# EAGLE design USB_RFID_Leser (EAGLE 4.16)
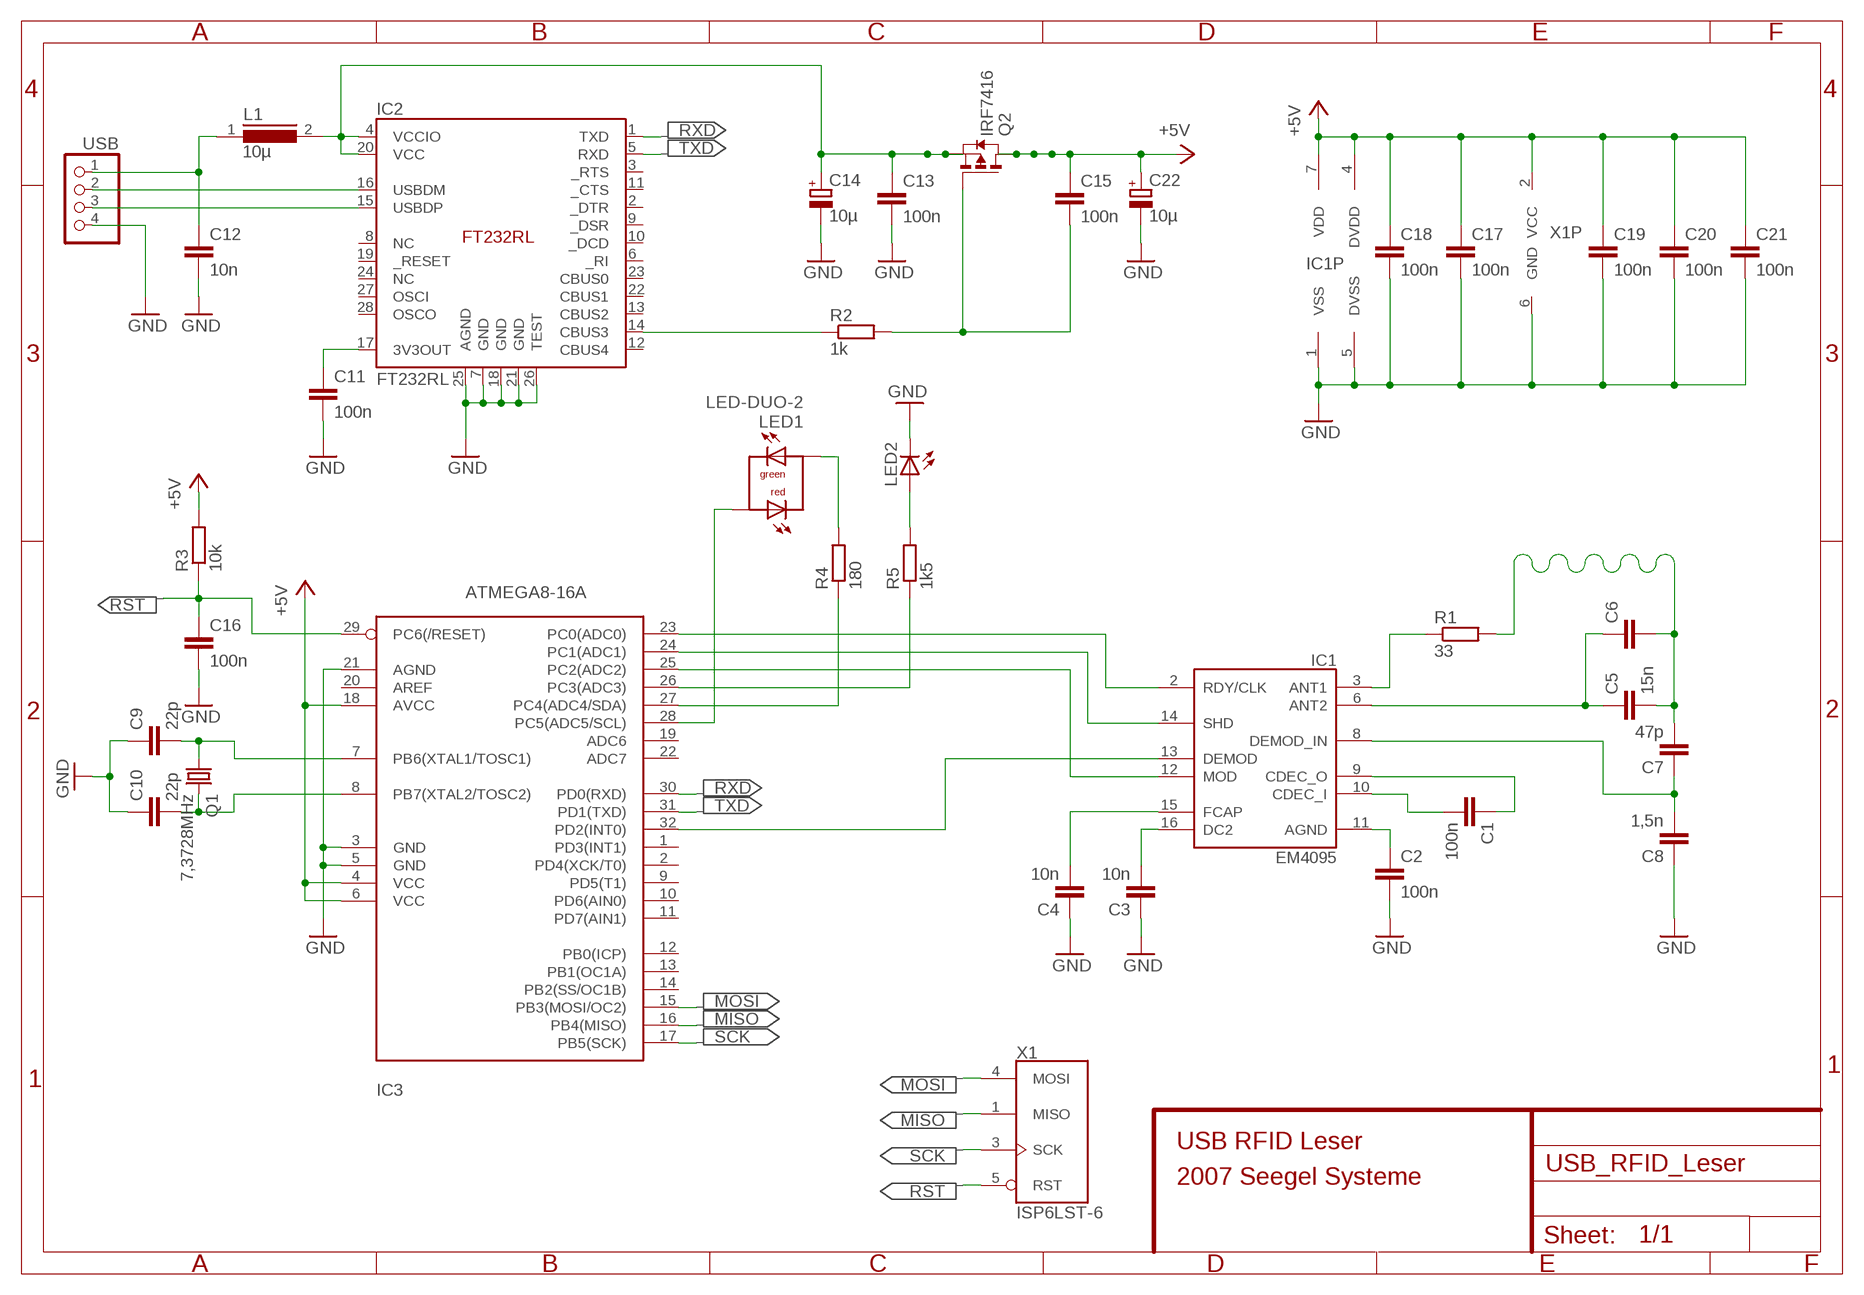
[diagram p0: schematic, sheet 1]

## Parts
C1  100n  C-EUC1206  [C1206]
C2  100n  C-EUC1206  [C1206]
C3  10n  C-EUC1206  [C1206]
C4  10n  C-EUC1206  [C1206]
C5  15n  C-EUC1206  [C1206]
C6  C-EUC1206  [C1206]
C7  47p  C-EUC1206  [C1206]
C8  1,5n  C-EUC1206  [C1206]
C9  22p  C-EUC1206  [C1206]
C10  22p  C-EUC1206  [C1206]
C11  100n  C-EUC1206  [C1206]
C12  10n  C-EUC1206  [C1206]
C13  100n  C-EUC1206  [C1206]
C14  10µ  CPOL-EU153CLV-0405  [153CLV-0405]
C15  100n  C-EUC1206  [C1206]
C16  100n  C-EUC1206  [C1206]
C17  100n  C-EUC1206  [C1206]
C18  100n  C-EUC1206  [C1206]
C19  100n  C-EUC1206  [C1206]
C20  100n  C-EUC1206  [C1206]
C21  100n  C-EUC1206  [C1206]
C22  10µ  CPOL-EU153CLV-0405  [153CLV-0405]
IC1  EM4095  [SO16]
IC2  FT232RL  [SSOP-28]
IC3  ATMEGA8-16A  [TQFP32-08]
L1  10µ  LQH3C  [LQH3C]
LED1  LED-DUO-2  [LED3MM]
LED2  LED3MM  [LED3MM]
Q1  7,3728MHz  CRYTALHC49S  [HC49/S]
Q2  IRF7416  PMOSSO8  [SO8]
R1  33  R-EU_R1206  [R1206]
R2  1k  R-EU_R1206  [R1206]
R3  10k  R-EU_R1206  [R1206]
R4  180  R-EU_R1206  [R1206]
R5  1k5  R-EU_R1206  [R1206]
USB  PINHD-1X4  [1X04]
X1  ISP6LST-6  [MA03-2]

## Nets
+5V: C15.1 C17.1 C18.1 C19.1 C20.1 C21.1 C22.+ IC1.4(DVDD) IC1.7(VDD) IC3.4(VCC) IC3.6(VCC) IC3.18(AVCC) Q2.5(D) Q2.6(D1) Q2.7(D2) Q2.8(D3) R3.2 X1.2(VCC)
GND: C2.2 C3.1 C4.1 C8.1 C9.1 C10.1 C11.2 C12.2 C13.2 C14.- C16.2 C17.2 C18.2 C19.2 C20.2 C21.2 C22.- IC1.1(VSS) IC1.5(DVSS) IC2.7(GND) IC2.18(GND) IC2.21(GND) IC2.25(AGND) IC2.26(TEST) IC3.3(GND) IC3.5(GND) IC3.21(AGND) LED2.K(C) USB.4 X1.6(GND)
MISO: IC3.16(PB4(MISO)) X1.1(MISO)
MOSI: IC3.15(PB3(MOSI/OC2)) X1.4(MOSI)
N$1: IC2.15(USBDP) USB.3
N$2: IC2.16(USBDM) USB.2
N$3: C1.2 IC1.10(CDEC_I)
N$4: C1.1 IC1.9(CDEC_O)
N$5: C2.1 IC1.11(AGND)
N$6: C3.2 IC1.16(DC2)
N$7: C4.2 IC1.15(FCAP)
N$8: IC1.3(ANT1) R1.1
N$9: IC1.2(RDY/CLK) IC3.23(PC0(ADC0))
N$10: C5.1 C6.1 IC1.6(ANT2)
N$11: C7.1 C8.2 IC1.8(DEMOD_IN)
N$12: C9.2 IC3.7(PB6(XTAL1/TOSC1)) Q1.1
N$13: C10.2 IC3.8(PB7(XTAL2/TOSC2)) Q1.2
N$14: IC1.13(DEMOD) IC3.32(PD2(INT0))
N$15: C11.1 IC2.17(3V3OUT)
N$16: C5.2 C6.2 C7.2 R1.2
N$17: C12.1 L1.1 USB.1
N$18: C13.1 C14.+ IC2.4(VCCIO) IC2.20(VCC) L1.2 Q2.1(S) Q2.2(S1) Q2.3(S2)
N$19: IC1.14(SHD) IC3.24(PC1(ADC1))
N$20: IC1.12(MOD) IC3.25(PC2(ADC2))
N$21: IC2.14(CBUS3) R2.1
N$22: C15.2 Q2.4(G) R2.2
N$23: IC3.26(PC3(ADC3)) R5.1
N$24: IC3.27(PC4(ADC4/SDA)) R4.1
N$25: LED1.K R4.2
N$26: IC3.28(PC5(ADC5/SCL)) LED1.A
N$27: LED2.A R5.2
RST: C16.1 IC3.29(PC6(/RESET)) R3.1 X1.5(RST)
RXD: IC2.1(TXD) IC3.30(PD0(RXD))
SCK: IC3.17(PB5(SCK)) X1.3(SCK)
TXD: IC2.5(RXD) IC3.31(PD1(TXD))
Unconnected: IC2.2(_DTR) IC2.3(_RTS) IC2.6(_RI) IC2.8(NC) IC2.9(_DSR) IC2.10(_DCD) IC2.11(_CTS) IC2.12(CBUS4) IC2.13(CBUS2) IC2.19(_RESET) IC2.22(CBUS1) IC2.23(CBUS0) IC2.24(NC) IC2.27(OSCI) IC2.28(OSCO) IC3.1(PD3(INT1)) IC3.2(PD4(XCK/T0)) IC3.9(PD5(T1)) IC3.10(PD6(AIN0)) IC3.11(PD7(AIN1)) IC3.12(PB0(ICP)) IC3.13(PB1(OC1A)) IC3.14(PB2(SS/OC1B)) IC3.19(ADC6) IC3.20(AREF) IC3.22(ADC7)

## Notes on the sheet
- USB RFID Leser
- 2007 Seegel Systeme

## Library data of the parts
C1-C13 C15-C21 = rcl:C-EU: CAPACITOR, European symbol
C14 C22 = rcl:CPOL-EU: POLARIZED CAPACITOR, European symbol
IC1 = emtec:EM4095: Read/Write analog front end for 125kHz RFID Basestation EM Microelectronic, http://www.emmicroelectronic.com
IC2 = ftdi4:FT232RL
IC3 = avr:ATMEGA8: MICROCONTROLLER 8 Kbytes FLASH 1 kbytes SRAM 512 bytes EEPROM USART 6-channel 10 bit ADC 2-channel 8 bit ADC
L1 = inductor-murata:LQH3C
LED1 = led:LED-DUO-2
LED2 = led:LED: LED
Q1 = crystal:CRYTAL: CRYSTAL
Q2 = zetex:PMOSSO8
R1-R5 = rcl:R-EU_: RESISTOR, European symbol
USB = pinhead:PINHD-1X4: PIN HEADER
X1 = avr:ISP6

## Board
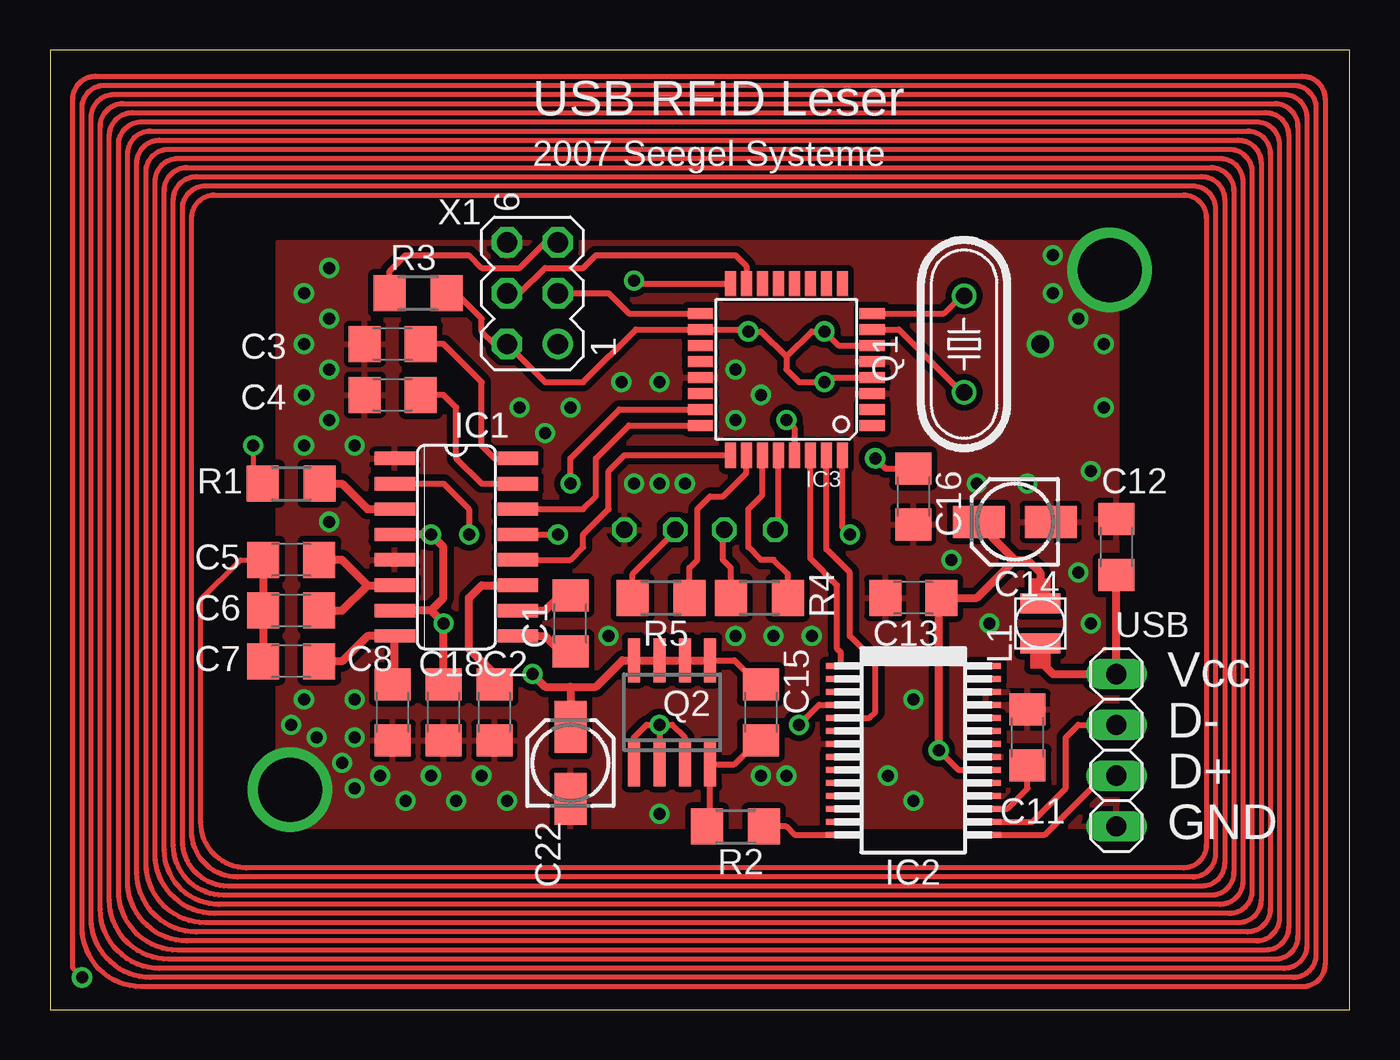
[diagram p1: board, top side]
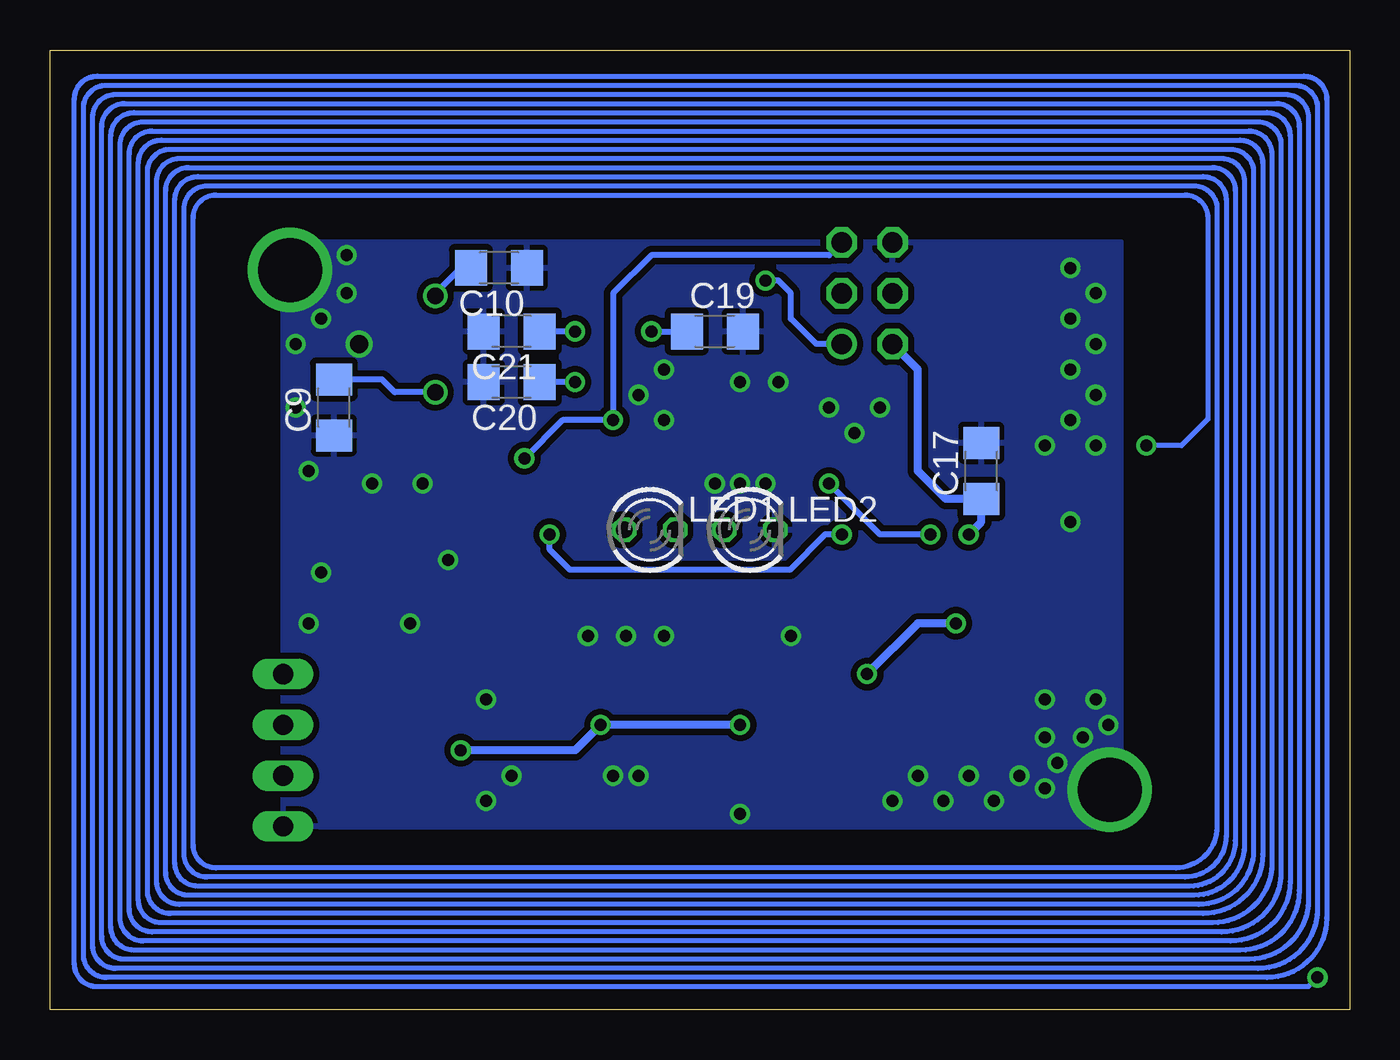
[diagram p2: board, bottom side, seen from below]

Size 65 x 48 mm. Coordinates in mm from the lower left corner, seen from the top.
Outline: 0,0 65,0 65,48 0,48 0,0
Copper layers (1*16): Top 0.035mm / dielectric 1.5mm / Bottom 0.035mm
Design rules "pcb-pool": minimum track width 6mil, minimum drill 12mil, track to track 6mil, track to pad 6mil, pad to pad 6mil, via to via 6mil, smd to smd 8mil, copper to edge 40mil, drill to drill 20mil, minimum pad ring 8mil, minimum via ring 8mil, stop-mask expansion 6mil, vias tented up to drill 0mil, thermal gap 10mil

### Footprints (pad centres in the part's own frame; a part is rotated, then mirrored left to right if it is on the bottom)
C1206 = smd 1.6 x 1.8: 1 -1.4,0; 2 1.4,0
153CLV-0405 = smd 2.6 x 1.6: + 1.8,0; - -1.8,0
SO16 = smd 0.66 x 2.032: 1 -4.445,-3.073; 2 -3.175,-3.073; 3 -1.905,-3.073; 4 -0.635,-3.073; 5 0.635,-3.073; 6 1.905,-3.073; 7 3.175,-3.073; 8 4.445,-3.073; 9 4.445,3.073; 10 3.175,3.073; 11 1.905,3.073; 12 0.635,3.073; 13 -0.635,3.073; 14 -1.905,3.073; 15 -3.175,3.073; 16 -4.445,3.073
SSOP-28 = smd 0.3 x 1.5: 1 -4.225,-3.625; 2 -3.575,-3.625; 3 -2.925,-3.625; 4 -2.275,-3.625; 5 -1.625,-3.625; 6 -0.975,-3.625; 7 -0.325,-3.625; 8 0.325,-3.625; 9 0.975,-3.625; 10 1.625,-3.625; 11 2.275,-3.625; 12 2.925,-3.625; 13 3.575,-3.625; 14 4.225,-3.625; 15 4.225,3.625; 16 3.575,3.625; 17 2.925,3.625; 18 2.275,3.625; 19 1.625,3.625; 20 0.975,3.625; 21 0.325,3.625; 22 -0.325,3.625; 23 -0.975,3.625; 24 -1.625,3.625; 25 -2.275,3.625; 26 -2.925,3.625; 27 -3.575,3.625; 28 -4.225,3.625
TQFP32-08 = smd 1.27 x 0.559: 1 -4.293,2.8; 2 -4.293,2; 3 -4.293,1.2; 4 -4.293,0.4; 5 -4.293,-0.4; 6 -4.293,-1.2; 7 -4.293,-2; 8 -4.293,-2.8; 17 4.293,-2.8; 18 4.293,-2; 19 4.293,-1.2; 20 4.293,-0.4; 21 4.293,0.4; 22 4.293,1.2; 23 4.293,2; 24 4.293,2.8 | smd 0.559 x 1.27: 9 -2.8,-4.293; 10 -2,-4.293; 11 -1.2,-4.293; 12 -0.4,-4.293; 13 0.4,-4.293; 14 1.2,-4.293; 15 2,-4.293; 16 2.8,-4.293; 25 2.8,4.293; 26 2,4.293; 27 1.2,4.293; 28 0.4,4.293; 29 -0.4,4.293; 30 -1.2,4.293; 31 -2,4.293; 32 -2.8,4.293
LQH3C = smd 1 x 2: 1 -1,0; 2 1,0
LED3MM = drill 0.813 octagon: A -1.27,0; K 1.27,0
HC49/S = drill 0.813 round: 1 -2.413,0; 2 2.413,0
SO8 = smd 0.6 x 2.2: 1 -1.905,-2.6; 2 -0.635,-2.6; 3 0.635,-2.6; 4 1.905,-2.6; 5 1.905,2.6; 6 0.635,2.6; 7 -0.635,2.6; 8 -1.905,2.6
R1206 = smd 1.6 x 1.803: 1 -1.422,0; 2 1.422,0
1X04 = drill 1.016 long: 1 -3.81,0; 2 -1.27,0; 3 1.27,0; 4 3.81,0
MA03-2 = drill 1.016 round: 1 -2.54,-1.27 | drill 1.016 octagon: 2 -2.54,1.27; 3 0,-1.27; 4 0,1.27; 5 2.54,-1.27; 6 2.54,1.27

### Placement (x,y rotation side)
C1  26.04,19.32 90 top
C2  22.23,14.88 270 top
C3  17.14,33.29 0 top
C4  17.14,30.75 0 top
C5  12.06,22.5 180 top
C6  12.06,19.95 180 top
C7  12.06,17.41 180 top
C8  17.14,14.88 90 top
C9  50.8,30.11 90 bottom
C10  42.55,37.1 180 bottom
C11  48.9,13.61 90 top
C12  53.34,23.13 90 top
C13  43.18,20.59 180 top
C14  48.26,24.4 180 top
C15  35.56,14.88 270 top
C16  43.18,25.67 270 top
C17  18.41,26.94 90 bottom
C18  19.68,14.88 270 top
C19  31.75,33.92 0 bottom
C20  41.91,31.38 180 bottom
C21  41.91,33.92 180 bottom
C22  26.04,12.34 90 top
IC1  20.32,23.13 270 top
IC2  43.18,12.97 270 top
IC3  36.83,32.02 180 top
L1  49.53,19.32 90 top
LED1  35,24 0 bottom
LED2  30,24 0 bottom
Q1  45.72,33.29 90 top
Q2  31.11,14.88 0 top
R1  12.06,26.3 180 top
R2  34.29,9.16 180 top
R3  18.41,35.83 0 top
R4  35.48,20.59 180 top
R5  30.56,20.59 180 top
USB  53.34,12.97 270 top
X1  24.13,35.83 90 top

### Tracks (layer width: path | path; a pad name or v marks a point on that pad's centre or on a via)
+5V  (via drill 0.6)
  Top 0.305: IC3.6 39.44,33.22 v38.73,33.92 38.1,33.92 36.83,32.66 | IC3.4 38.97,31.62 v38.73,31.38 37.47,31.38 36.83,32.02 36.83,32.66 | C15.1 35.56,16.14 34.23,17.48 Q2.5 | Q2.6 31.75,17.41 31.81,17.48 | Q2.7 30.48,17.41 30.54,17.48 | Q2.8 29.21,17.41 29.27,17.48 | 36.83,32.66 35.56,33.92 v34.92,33.92 34.83,34.02 IC3.18 29.3,34.02 26.67,31.38 24.77,31.38 X1.2 22.23,33.29 21.59,33.92 21.59,34.56 20.32,35.83 R3.2
  Top 0.406: 19.05,19.95 v19.68,19.32 C18.1 19.05,16.14 | 19.05,19.95 IC1.7 | 19.05,19.95 19.68,20.59 19.68,23.13 v19.05,23.77 IC1.4 17.14,23.77 | 31.81,17.48 Q2.5 | 30.54,17.48 Q2.6 | 29.27,17.48 Q2.7 | Q2.8 28.64,17.48 27.3,16.14 26.04,16.14 | 26.04,16.14 24.77,16.14 v24.13,16.78 | 26.04,16.14 C22.+
  Bottom 0.305: v34.92,33.92 C19.1 | v38.73,33.92 C21.1 | v38.73,31.38 C20.1
  Bottom 0.406: v19.05,23.77 18.41,24.4 C17.1 20.19,25.54 21.59,26.94 21.59,32.02 X1.2 | v24.13,16.78 21.59,19.32 v19.68,19.32
GND  (via drill 0.6, 0.9, 3.2)
  other vias: 12,11 34.29,32.02 35.56,30.75 34.29,29.48 23.5,30.11 26.04,30.11 28.57,31.38 30.48,31.38 12.7,33.29 13.97,32.02 12.7,30.75 13.97,29.48 12.7,28.21 15.24,28.21 15.24,11.06 17.78,10.43 19.05,11.7 20.32,10.43 21.59,11.7 22.86,10.43 35.56,11.7 36.83,11.7 43.18,15.51 43.18,10.43 52.07,26.94 49.53,33.29 46.99,19.32 52.07,19.32 51.44,21.86 13.97,24.4 16.51,11.7 15.24,13.61 15.24,15.51 13.34,13.61 12.7,15.51 14.61,12.34 12.06,14.24 38.1,18.68 36.2,18.68 34.29,18.68 27.94,18.68 31.75,26.3 29.21,26.3 30.48,26.3 24.77,28.84 12.7,35.83 13.97,37.1 13.97,34.56 30.48,9.79 41.91,11.7 45.09,22.5 46.35,26.3 48.9,26.3 52.7,33.29 52.7,30.11 53,37 50.16,37.73 50.16,35.83 51.44,34.56
  pour Bottom (isolate 0.305): 11.43,38.37 53.34,38.37 53.34,9.16 11.43,9.16
  pour Top (isolate 0.305): 11.43,38.37 53.34,38.37 53.34,9.16 11.43,9.16
MISO  (via drill 0.6)
  Top 0.305: IC3.16 29.36,36.31 v29.21,36.47
  Bottom 0.305: X1.1 26.67,33.29 27.94,34.56 27.94,35.83 28.57,36.47 v29.21,36.47
MOSI
  Top 0.305: X1.4 23.5,35.83 24.77,37.1 26.67,37.1 27.3,37.73 34.29,37.73 34.83,37.2 IC3.15
N$1
  Top 0.305: IC2.15 49.75,8.74 52.7,11.7 USB.3
N$2
  Top 0.305: IC2.16 49.13,9.39 50.8,11.06 50.8,13.61 51.44,14.24 USB.2
N$3
  Top 0.406: IC1.10 24.77,19.95 25.4,20.59 26.04,20.59 C1.2
N$4
  Top 0.406: IC1.9 24.77,18.68 25.4,18.05 26.04,18.05 C1.1
N$5
  Top 0.406: IC1.11 21.59,21.23 20.95,20.59 20.95,18.05 22.23,16.78 C2.1 21.59,16.14
N$6
  Top 0.305: IC1.16 22.23,27.57 21.59,28.21 21.59,31.38 19.68,33.29 C3.2
N$7
  Top 0.305: IC1.15 21.59,26.3 20.32,27.57 20.32,30.11 19.68,30.75 C4.2
N$8
  Top 0.406: IC1.3 15.88,25.04 14.61,26.3 R1.1 13.34,26.3
N$9  (via drill 0.6)
  Top 0.305: IC1.2 19.68,26.3 20.95,25.04 v20.95,23.77 | IC3.23 28.48,30.02 26.04,27.57 v26.04,26.3
  Bottom 0.305: v20.95,23.77 23.5,23.77 v26.04,26.3
N$10
  Top 0.406: 15.88,21.23 IC1.6 | 15.88,21.23 14.61,22.5 C5.1 13.34,21.86 | C6.1 14.61,19.95 15.88,21.23
N$11
  Top 0.305: C8.2 17.14,16.14 17.25,16.25
  Top 0.406: 13.34,16.78 C7.1 14.61,17.41 15.88,18.68 IC1.8 17.25,16.25
N$12
  Top 0.305: IC3.7 42.45,34.02 45.59,30.88 Q1.1
  Bottom 0.305: C9.2 48.39,31.52 47.75,30.88 Q1.1
N$13
  Top 0.305: Q1.2 45.72,35.83 44.71,34.82 IC3.8
  Bottom 0.305: Q1.2 45.72,35.83 44.45,37.1 C10.2
N$14  (via drill 0.6)
  Top 0.305: IC3.32 39.63,24.14 v40.01,23.77 | IC1.13 v25.4,23.77
  Bottom 0.305: v25.4,23.77 26.23,23.77 28,22 39,22 40.01,23 v40.01,23.77
N$15
  Top 0.305: IC2.17 47.88,10.04 48.9,11.06 C11.1 48.9,12.34
N$16  (via drill 0.6)
  Top 0.254: v1.6,1.6 1.14,2.06 1.14,45.55 arc-90 2.29,46.69 62.64,46.69 arc-90 63.78,45.55 63.78,2.29 arc-90 62.64,1.14 4.57,1.14 arc-90 1.6,4.12 1.6,45.09 arc-90 2.74,46.23 62.18,46.23 arc-90 63.32,45.09 63.32,2.74 arc-90 62.18,1.6 5.03,1.6 arc-90 2.06,4.57 2.06,44.63 arc-90 3.2,45.78 61.72,45.78 arc-90 62.87,44.63 62.87,3.2 arc-90 61.72,2.06 5.49,2.06 arc-90 2.52,5.03 2.52,44.18 arc-90 3.66,45.32 61.27,45.32 arc-90 62.41,44.18 62.41,3.66 arc-90 61.27,2.52 5.94,2.52 arc-90 2.97,5.49 2.97,43.72 arc-90 4.12,44.86 60.81,44.86 arc-90 61.95,43.72 61.95,4.12 arc-90 60.81,2.97 6.4,2.97 arc-90 3.43,5.94 3.43,43.26 arc-90 4.57,44.41 60.35,44.41 arc-90 61.49,43.26 61.49,4.57 arc-90 60.35,3.43 6.86,3.43 arc-90 3.89,6.4 3.89,42.81 arc-90 5.03,43.95 59.89,43.95 arc-90 61.04,42.81 61.04,5.03 arc-90 59.89,3.89 7.32,3.89 arc-90 4.34,6.86 4.34,42.35 arc-90 5.49,43.49 59.44,43.49 arc-90 60.58,42.35 60.58,5.49 arc-90 59.44,4.34 7.77,4.34 arc-90 4.8,7.31 4.8,41.89 arc-90 5.94,43.03 58.98,43.03 arc-90 60.12,41.89 60.12,5.94 arc-90 58.98,4.8 8.23,4.8 arc-90 5.26,7.77 5.26,41.43 arc-90 6.4,42.58 58.52,42.58 arc-90 59.66,41.43 59.66,6.4 arc-90 58.52,5.26 8.46,5.26 arc-90 5.71,8 5.71,40.98 arc-90 6.86,42.12 58.06,42.12 arc-90 59.21,40.98 59.21,6.86 arc-90 58.06,5.71 8.69,5.71 arc-90 6.17,8.23 6.17,40.52 arc-90 7.32,41.66 57.61,41.66 arc-90 58.75,40.52 58.75,7.31 arc-90 57.61,6.17 8.91,6.17 arc-90 6.63,8.46 6.63,40.06 arc-90 7.77,41.2 57.15,41.2 arc-90 58.29,40.06 58.29,7.77 arc-90 57.15,6.63 9.37,6.63 arc-90 7.09,8.91 7.09,39.6 arc-90 8.23,40.75 56.69,40.75 arc-90 57.84,39.6 57.84,8.23 arc-90 56.69,7.09 9.83,7.09 arc-90 7.54,9.37 7.54,20.51 9.53,22.5 C5.2
  Top 0.254: R1.2 10.16,26.79 v10.16,28.21
  Top 0.305: C5.2 10.79,21.86
  Top 0.406: C5.2 10.66,19.45 10.79,19.32 C6.2 10.66,16.91 10.79,16.78 C7.2
  Bottom 0.254: v1.6,1.6 2.06,1.14 62.64,1.14 arc90 63.78,2.29 63.78,45.55 arc90 62.64,46.69 2.29,46.69 arc90 1.14,45.55 1.14,4.57 arc90 4.12,1.6 62.18,1.6 arc90 63.32,2.74 63.32,45.09 arc90 62.18,46.23 2.74,46.23 arc90 1.6,45.09 1.6,5.03 arc90 4.57,2.06 61.72,2.06 arc90 62.87,3.2 62.87,44.63 arc90 61.72,45.78 3.2,45.78 arc90 2.06,44.63 2.06,5.49 arc90 5.03,2.52 61.27,2.52 arc90 62.41,3.66 62.41,44.18 arc90 61.27,45.32 3.66,45.32 arc90 2.52,44.18 2.52,5.94 arc90 5.49,2.97 60.81,2.97 arc90 61.95,4.12 61.95,43.72 arc90 60.81,44.86 4.12,44.86 arc90 2.97,43.72 2.97,6.4 arc90 5.94,3.43 60.35,3.43 arc90 61.49,4.57 61.49,43.26 arc90 60.35,44.41 4.57,44.41 arc90 3.43,43.26 3.43,6.86 arc90 6.4,3.89 59.89,3.89 arc90 61.04,5.03 61.04,42.81 arc90 59.89,43.95 5.03,43.95 arc90 3.89,42.81 3.89,7.31 arc90 6.86,4.34 59.44,4.34 arc90 60.58,5.49 60.58,42.35 arc90 59.44,43.49 5.49,43.49 arc90 4.34,42.35 4.34,7.77 arc90 7.32,4.8 58.98,4.8 arc90 60.12,5.94 60.12,41.89 arc90 58.98,43.03 5.94,43.03 arc90 4.8,41.89 4.8,8 arc90 7.54,5.26 58.52,5.26 arc90 59.66,6.4 59.66,41.43 arc90 58.52,42.58 6.4,42.58 arc90 5.26,41.43 5.26,8.23 arc90 7.77,5.71 58.06,5.71 arc90 59.21,6.86 59.21,40.98 arc90 58.06,42.12 6.86,42.12 arc90 5.71,40.98 5.71,8.46 arc90 8,6.17 57.61,6.17 arc90 58.75,7.31 58.75,40.52 arc90 57.61,41.66 7.32,41.66 arc90 6.17,40.52 6.17,8.69 arc90 8.23,6.63 57.15,6.63 arc90 58.29,7.77 58.29,40.06 arc90 57.15,41.2 7.77,41.2 arc90 6.63,40.06 6.63,9.14 arc90 8.69,7.09 56.69,7.09 arc90 57.84,8.23 57.84,39.6 arc90 56.69,40.75 8.23,40.75 arc90 7.09,39.6 7.09,29.53 8.41,28.21 v10.16,28.21
N$17
  Top 0.406: C12.1 USB.1 50.16,16.78 49.53,17.41 L1.1
N$18  (via drill 0.6)
  Top 0.305: IC2.20 45.42,11.99 v44.45,12.97 | 44.45,20.59 C13.1 | IC2.4 38.47,15.25 v37.47,14.24 | v30.48,14.24 Q2.2 | Q2.1 29.21,13.61 29.84,14.24 v30.48,14.24 | Q2.3 31.75,13.61 31.11,14.24 v30.48,14.24
  Top 0.406: L1.2 49.53,21.86 48.9,22.5 48.26,22.5 | C13.1 46.35,20.59 48.26,22.5 | v44.45,12.97 44.45,20.59 | C14.+ 46.35,24.4 48.26,22.5
  Bottom 0.406: v44.45,12.97 38.73,12.97 v37.47,14.24 v30.48,14.24
N$19
  Top 0.305: IC3.24 28.95,29.22 27.3,27.57 27.3,25.67 26.67,25.04 IC1.14
N$20
  Top 0.305: IC3.25 28.73,27.73 27.94,26.94 27.94,25.04 26.67,23.77 26.67,23.13 26.04,22.5 IC1.12
N$21
  Top 0.305: R2.1 36.83,9.16 37.24,8.74 IC2.14
N$22
  Top 0.305: R2.2 33.02,9.16 Q2.4 34.23,12.28 35.56,13.61 C15.2
N$23
  Top 0.305: R5.1 31.98,22.09 32.38,22.5 32.38,25.04 33.02,25.67 33.66,25.67 34.83,26.84 IC3.26
N$24
  Top 0.305: IC3.27 35.63,25.74 34.92,25.04 34.92,23.13 35.56,22.5 36.2,22.5 36.9,21.79 R4.1
N$25
  Top 0.305: R4.2 34.06,22.09 33.66,22.5 33.66,23.77 33.73,23.84 LED1.K
N$26
  Top 0.305: LED1.A 36.27,24.09 36.43,24.25 IC3.28
N$27
  Top 0.305: LED2.A 31.27,23.92 29.14,21.79 R5.2
RST  (via drill 0.6)
  Top 0.305: IC3.29 37.23,29.08 v36.83,29.48 | C16.1 41.78,27.07 v41.27,27.57 | X1.5 24.77,38.37 23.5,37.1 21.59,37.1 20.95,37.73 17.78,37.73 16.99,36.95 R3.1
  Bottom 0.305: X1.5 26.04,37.73 34.92,37.73 36.83,35.83 v36.83,29.48 39.37,29.48 v41.27,27.57
RXD
  Top 0.305: IC3.30 38.03,22.57 39.37,21.23 39.37,18.05 39.55,17.86 IC2.1
SCK
  Top 0.305: IC3.17 28.95,34.82 27.94,35.83 X1.3
TXD
  Top 0.305: IC3.31 38.83,23.04 40.01,21.86 40.01,18.68 41.27,17.41 41.27,14.88 40.99,14.6 IC2.5

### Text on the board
tNames: USB RFID Leser | 2007 Seegel Systeme | Vcc | D- | D+ | GND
